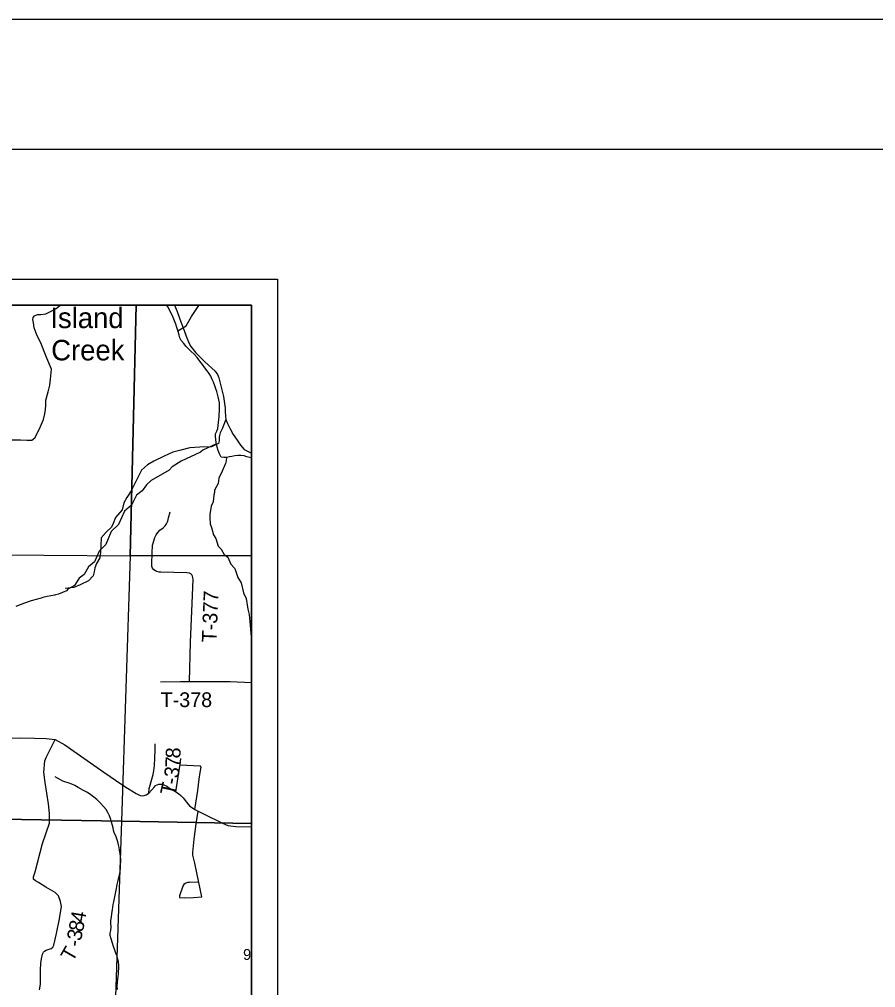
# Model space of a CAD drawing. Extents: x -19 to 40.8, y -1.8 to 26.1.
# Drawn here: x 8.007 to 11.302, y 18.273 to 22 of the extents above; entities that cross this region are included whole.
import ezdxf

# ---------------------------------------------------------------- set-up
doc = ezdxf.new("R2010")
doc.units = 0
for name, color, linetype in [('Default', 7, 'Continuous'), ('GM_X_Corporation', 7, 'Continuous'), ('GM_X_Corporation_Text', 7, 'Continuous'), ('GM_X_Section', 7, 'Continuous'), ('GM_X_Section_Text', 7, 'Continuous'), ('GM_X_State_Route', 7, 'Continuous'), ('GM_X_Township_Road_Text', 7, 'Continuous'), ('RW_P_Text', 7, 'Continuous'), ('SH_Border', 7, 'Continuous'), ('SH_Cut_Line', 7, 'Continuous'), ('SH_Data', 7, 'Continuous')]:
    doc.layers.add(name, color=color, linetype=linetype)

msp = doc.modelspace()

# ---------------------------------------------------------------- linework, layer by layer
at = {"layer": 'Default'}
for points in [[(8.4567, 20.9), (7.4553, 20.9), (7.4345, 19.9428), (8.4338, 19.9356)], [(8.9, 19.9364), (8.9, 20.9), (8.4567, 20.9), (8.4338, 19.9356)], [(8.9, 18.9056), (8.9, 19.9364), (8.4338, 19.9356), (8.4001, 18.9137)], [(8.9, 17.9188), (8.9, 18.9056), (8.4001, 18.9137), (8.3666, 17.9389)]]:
    msp.add_lwpolyline(points, close=True, dxfattribs=at)
at = {"layer": 'GM_X_Corporation'}
for points in [[(8.6043, 20.9), (8.6136, 20.8758), (8.625, 20.846), (8.6406, 20.8029), (8.6489, 20.7811), (8.6608, 20.7525), (8.6667, 20.7412), (8.6863, 20.7171), (8.7211, 20.6815), (8.7598, 20.6456), (8.7697, 20.6333), (8.774, 20.6199), (8.7922, 20.5483), (8.7989, 20.5039), (8.7993, 20.4907), (8.7999, 20.4734), (8.8013, 20.4597), (8.8078, 20.4447), (8.8177, 20.4247), (8.8301, 20.4027), (8.8446, 20.3799), (8.8573, 20.3607), (8.8723, 20.3446), (8.8946, 20.3324), (8.9, 20.331)], [(7.7512, 19.2321), (7.7801, 19.2311), (7.8722, 19.2319), (8.0068, 19.2346), (8.0647, 19.2339), (8.1097, 19.2329), (8.145, 19.2283)], [(8.145, 19.2283), (8.1816, 19.2078), (8.217, 19.1837), (8.332, 19.1029), (8.4012, 19.0553), (8.4235, 19.0407), (8.4559, 19.0204), (8.4637, 19.0168), (8.472, 19.0135), (8.4789, 19.0121), (8.487, 19.0126), (8.4951, 19.0157), (8.5047, 19.0224), (8.5163, 19.0348), (8.5265, 19.0458), (8.5311, 19.051), (8.5367, 19.0544), (8.5433, 19.0563), (8.5487, 19.0568), (8.5555, 19.0565), (8.5632, 19.0535), (8.5741, 19.0485), (8.5814, 19.0441), (8.595, 19.035), (8.6092, 19.0269), (8.6189, 19.02), (8.6285, 19.0134), (8.6373, 19.004), (8.6502, 18.9871), (8.662, 18.973), (8.6822, 18.9594), (8.6951, 18.9527), (8.7383, 18.9308), (8.7657, 18.9175), (8.7892, 18.9066), (8.8093, 18.8979), (8.84, 18.8939), (8.9, 18.8929)]]:
    msp.add_lwpolyline(points, dxfattribs=at)
at = {"layer": 'GM_X_Section'}
for points in [[(8.9, 20.3125), (8.8936, 20.3142), (8.8818, 20.3169), (8.8714, 20.3196), (8.8596, 20.3219), (8.8474, 20.3219), (8.836, 20.3208), (8.8251, 20.3178), (8.8153, 20.316), (8.8043, 20.3141), (8.7933, 20.3141), (8.7833, 20.315), (8.7765, 20.3273), (8.7719, 20.3413), (8.7681, 20.3537), (8.7645, 20.3711), (8.7634, 20.3829), (8.7615, 20.3942), (8.7623, 20.4045), (8.7674, 20.4146), (8.7708, 20.4257), (8.7736, 20.4479), (8.7751, 20.4598), (8.7756, 20.4697), (8.7764, 20.4804), (8.7768, 20.4918), (8.7776, 20.5013), (8.7776, 20.5147), (8.7769, 20.5245), (8.7746, 20.5363), (8.772, 20.5472), (8.7694, 20.5574), (8.7668, 20.568), (8.7635, 20.5782), (8.7589, 20.5898), (8.7539, 20.6041), (8.7487, 20.6146), (8.7433, 20.6266), (8.7369, 20.6371), (8.7298, 20.6472), (8.7203, 20.6583), (8.7119, 20.6713), (8.7016, 20.6851), (8.691, 20.6981), (8.6791, 20.7114), (8.6682, 20.7213), (8.6588, 20.7313), (8.6493, 20.7409), (8.6395, 20.752), (8.6292, 20.7643), (8.6243, 20.7744), (8.6221, 20.7842), (8.6179, 20.7993), (8.6132, 20.8136), (8.6087, 20.8268), (8.6045, 20.8396), (8.5991, 20.8524), (8.591, 20.8689), (8.5777, 20.8936), (8.5746, 20.9)], [(8.6172, 20.8013), (8.6491, 20.8201), (8.6696, 20.8566), (8.6973, 20.8982), (8.698, 20.9)], [(8.7654, 20.3666), (8.7129, 20.3425), (8.704, 20.3344), (8.6294, 20.2993), (8.5946, 20.2781), (8.5831, 20.2654), (8.5138, 20.225), (8.496, 20.2091), (8.4797, 20.1857), (8.4581, 20.1689), (8.4383, 20.1305), (8.4119, 20.1073), (8.3889, 20.0563), (8.3607, 20.0295), (8.3396, 19.979), (8.3136, 19.9534), (8.2954, 19.9124), (8.2727, 19.8934), (8.2566, 19.863), (8.2364, 19.8494), (8.2191, 19.8209), (8.1936, 19.8072), (8.1885, 19.8006), (8.1577, 19.788), (8.1464, 19.7847), (8.1426, 19.7839), (8.1132, 19.7789), (8.0967, 19.7752), (8.0903, 19.772), (8.0527, 19.7623), (8.026, 19.7527), (7.9933, 19.74)], [(8.8044, 20.3141), (8.8032, 20.3014), (8.8, 20.2911), (8.7869, 20.2612), (8.7749, 20.2339), (8.7718, 20.2137), (8.7583, 20.1884), (8.7581, 20.1785), (8.7548, 20.1697), (8.7522, 20.1437), (8.7446, 20.1261), (8.7402, 20.0948), (8.7393, 20.0819), (8.7416, 20.0579), (8.7468, 20.0439), (8.7537, 20.0162), (8.763, 20.0015), (8.7714, 19.9724), (8.7841, 19.9604), (8.795, 19.94), (8.8088, 19.9296), (8.821, 19.9032), (8.8356, 19.887), (8.8472, 19.8514), (8.8608, 19.8319), (8.8698, 19.7924), (8.8799, 19.7717), (8.8867, 19.7303), (8.8916, 19.709), (8.8945, 19.6691), (8.8967, 19.6513), (8.8984, 19.6231), (8.8997, 19.6094), (8.8998, 19.5855), (8.9, 19.5845)], [(8.3819, 18.8462), (8.3781, 18.8572), (8.3729, 18.8669), (8.3687, 18.8778), (8.3673, 18.888), (8.3647, 18.8978), (8.3616, 18.9103), (8.3586, 18.9209), (8.3533, 18.9352), (8.3468, 18.9479), (8.3404, 18.9584), (8.3312, 18.9706), (8.3191, 18.9832), (8.305, 18.9972), (8.2936, 19.0064), (8.2816, 19.0151), (8.2684, 19.0239), (8.2541, 19.0322), (8.2332, 19.0437), (8.2197, 19.0509), (8.2089, 19.0559), (8.195, 19.0612), (8.1854, 19.0643), (8.1746, 19.0685), (8.1646, 19.0728), (8.1538, 19.0793), (8.1449, 19.0847)], [(8.3847, 18.2669), (8.3832, 18.2787), (8.3839, 18.2935), (8.3857, 18.3065), (8.3866, 18.3164), (8.3882, 18.3268), (8.3886, 18.3363), (8.3891, 18.3462), (8.3894, 18.3591), (8.3886, 18.3724), (8.386, 18.3845), (8.383, 18.3943), (8.3785, 18.406), (8.3739, 18.418), (8.3697, 18.4312), (8.3651, 18.4451), (8.3596, 18.4609), (8.3562, 18.4737), (8.3559, 18.4832), (8.3583, 18.4928), (8.3597, 18.5069), (8.3593, 18.521), (8.3593, 18.5324), (8.3612, 18.545), (8.3631, 18.5588), (8.3649, 18.5729), (8.3668, 18.5836), (8.3684, 18.5936), (8.37, 18.6031), (8.3734, 18.6169), (8.3757, 18.6288), (8.378, 18.6418), (8.3806, 18.6556), (8.3831, 18.6709), (8.3865, 18.6858), (8.3895, 18.6973), (8.3933, 18.7108), (8.3945, 18.7207), (8.3956, 18.7344), (8.3964, 18.747), (8.3972, 18.7573), (8.3973, 18.7668), (8.3946, 18.7899), (8.3927, 18.8024), (8.3905, 18.8123), (8.3879, 18.8225), (8.3853, 18.8349), (8.3819, 18.8462)]]:
    msp.add_lwpolyline(points, dxfattribs=at)
at = {"layer": 'GM_X_State_Route'}
for p, q in [((8.6092, 19.0269), (8.6243, 19.1254)), ((8.6252, 19.1313), (8.7021, 19.1276))]:
    msp.add_line(p, q, dxfattribs=at)
for points in [[(8.9, 15.8791), (8.9, 20.9), (4.4356, 20.9), (4.4289, 20.4268), (4.4141, 19.3749), (4.4038, 18.6476), (4.3932, 17.8891)], [(8.127, 20.6156), (8.1309, 20.6537), (8.1123, 20.6957), (8.1025, 20.7212), (8.0898, 20.7548), (8.0749, 20.7818), (8.0643, 20.8125), (8.0611, 20.8324), (8.0592, 20.8452), (8.0596, 20.8526), (8.0651, 20.859), (8.0766, 20.8637), (8.0889, 20.8643), (8.1081, 20.8669), (8.1272, 20.8761), (8.1488, 20.887), (8.1608, 20.898), (8.1652, 20.9)], [(8.0401, 20.3804), (8.0547, 20.3801), (8.0663, 20.3896), (8.0838, 20.4241), (8.1, 20.46), (8.1047, 20.4818), (8.1078, 20.4987), (8.1086, 20.5152), (8.1089, 20.5343), (8.1171, 20.5669), (8.1246, 20.5917), (8.127, 20.6156)], [(8.8013, 20.4597), (8.7875, 20.4237), (8.7798, 20.4084), (8.7759, 20.3931), (8.7762, 20.3779), (8.7733, 20.368), (8.7467, 20.355), (8.7013, 20.353), (8.6624, 20.3512), (8.6278, 20.3415), (8.5969, 20.3345), (8.5646, 20.3187), (8.5245, 20.3001), (8.5005, 20.2853), (8.477, 20.2651), (8.4577, 20.2264), (8.4368, 20.1861), (8.4198, 20.1604), (8.4092, 20.1393), (8.4021, 20.1122), (8.3762, 20.0832), (8.3679, 20.0595), (8.3609, 20.0454), (8.3405, 20.026), (8.3219, 20.0048), (8.3205, 19.9763), (8.3187, 19.9496), (8.3161, 19.9272), (8.3036, 19.9057), (8.2967, 19.8896), (8.2951, 19.8732), (8.2912, 19.858), (8.273, 19.8386), (8.2411, 19.8236), (8.2163, 19.8133), (8.1831, 19.8097)], [(7.9723, 20.3815), (8.0117, 20.3821), (8.0352, 20.3804), (8.0401, 20.3804)], [(8.661, 19.4516), (8.6659, 19.6026), (8.6709, 19.7225), (8.6755, 19.8439), (8.6749, 19.8515), (8.6735, 19.8573), (8.6711, 19.8617), (8.6673, 19.8656), (8.6616, 19.8686), (8.6516, 19.8702), (8.5517, 19.872), (8.5449, 19.873), (8.5359, 19.8748), (8.5303, 19.877), (8.524, 19.8818), (8.5196, 19.8876), (8.5172, 19.8948), (8.5162, 19.9039), (8.5176, 19.9458), (8.5198, 19.9761), (8.5216, 19.9841), (8.5287, 20.0056), (8.5333, 20.0156), (8.5397, 20.025), (8.5473, 20.034), (8.5597, 20.0427), (8.5682, 20.0511), (8.5734, 20.0583), (8.5784, 20.0687), (8.5808, 20.0814), (8.5868, 20.1047)], [(8.5494, 19.4507), (8.6269, 19.4514), (8.6429, 19.4516), (8.661, 19.4516), (8.7408, 19.4516), (8.8187, 19.4517), (8.9, 19.4477)], [(8.0618, 18.6999), (8.0619, 18.7037), (8.067, 18.7188), (8.0959, 18.8284), (8.1228, 18.9066), (8.1228, 18.9437), (8.1187, 18.9808), (8.1059, 19.0624), (8.1007, 19.1029), (8.1044, 19.146), (8.1093, 19.1595), (8.145, 19.2283)], [(8.5047, 19.0224), (8.5064, 19.0393), (8.5097, 19.0521), (8.5138, 19.0668), (8.5213, 19.0932), (8.5244, 19.1084), (8.527, 19.1289), (8.5281, 19.1572), (8.529, 19.1886), (8.5298, 19.2112)], [(8.6243, 19.1254), (8.6252, 19.1313), (8.6282, 19.1549)], [(8.6822, 18.9594), (8.6937, 19.0327), (8.6983, 19.076), (8.7031, 19.1016), (8.706, 19.1214), (8.7021, 19.1276)], [(8.6937, 18.6789), (8.6618, 18.6781), (8.654, 18.6777), (8.6454, 18.6745), (8.6402, 18.6708), (8.6365, 18.6643), (8.623, 18.6263), (8.6225, 18.6199), (8.6421, 18.6197), (8.6774, 18.6207), (8.7095, 18.6231), (8.6976, 18.6786), (8.6816, 18.752), (8.6745, 18.783), (8.6741, 18.794), (8.6753, 18.8067), (8.6801, 18.8451), (8.6876, 18.9039), (8.6951, 18.9527)], [(8.0839, 18.2651), (8.0887, 18.2864), (8.0884, 18.3109), (8.0882, 18.3422), (8.089, 18.3657), (8.0921, 18.3847), (8.0962, 18.4017), (8.0993, 18.4099), (8.1037, 18.414), (8.11, 18.4178), (8.1291, 18.4239), (8.1361, 18.4298), (8.14, 18.4366), (8.1494, 18.482), (8.1611, 18.5378), (8.1695, 18.5863), (8.1651, 18.6049), (8.1577, 18.6262), (8.1446, 18.6398), (8.1088, 18.66), (8.0804, 18.6781), (8.0684, 18.6846), (8.0616, 18.6912), (8.0618, 18.6999)]]:
    msp.add_lwpolyline(points, dxfattribs=at)
at = {"layer": 'RW_P_Text'}
for points in [[(7.4345, 19.9428), (8.4338, 19.9356), (8.4001, 18.9137), (7.3987, 18.9308)], [(7.3987, 18.9308), (8.4001, 18.9137), (8.3666, 17.9389), (7.3559, 17.9489)]]:
    msp.add_lwpolyline(points, close=True, dxfattribs=at)
at = {"layer": 'SH_Border'}
msp.add_lwpolyline([(1.5, 21.5), (33.5, 21.5), (33.5, 0.5), (1.5, 0.5)], close=True, dxfattribs=at)
at = {"layer": 'SH_Cut_Line'}
msp.add_lwpolyline([(0, 0), (34, 0), (34, 22), (0, 22)], close=True, dxfattribs=at)
at = {"layer": 'SH_Data'}
for p, q in [((2, 21), (9, 21)), ((9, 21), (9, 14)), ((2.1, 20.9), (8.9, 20.9)), ((8.9, 20.9), (8.9, 14.1))]:
    msp.add_line(p, q, dxfattribs=at)

# ---------------------------------------------------------------- texts
at = {"layer": 'GM_X_Corporation_Text'}
for s, p in [('Island', (8.1261, 20.8117)), ('Creek', (8.1294, 20.6875))]:
    msp.add_text(s, height=0.07898, rotation=0, dxfattribs=at).set_placement(p)
at = {"layer": 'GM_X_Section_Text'}
msp.add_text('9', height=0.0419, rotation=0, dxfattribs=at).set_placement((8.8678, 18.3801))
at = {"layer": 'GM_X_Township_Road_Text'}
for s, height, rotation, p in [('T-377', 0.05682, 87.755, (8.7655, 19.6015)), ('T-378', 0.05682, 0, (8.5503, 19.3531)), ('8', 0.0568, 88.0149, (8.6263, 19.1549)), ('7', 0.0568, 87.8139, (8.625, 19.1197)), ('3', 0.0568, 80.2124, (8.6182, 19.0771)), ('T', 0.0568, 77.1955, (8.6031, 19.0097)), ('-', 0.0568, 77.5076, (8.6125, 19.0514)), ('4', 0.0568, 79.9925, (8.2581, 18.521)), ('8', 0.0568, 78.7514, (8.251, 18.4854)), ('3', 0.0568, 78.3461, (8.2439, 18.4507)), ('-', 0.0568, 81.9377, (8.2407, 18.4285)), ('T', 0.0568, 59.8697, (8.2116, 18.3693))]:
    msp.add_text(s, height=height, rotation=rotation, dxfattribs=at).set_placement(p)

doc.saveas('drawing.dxf')
